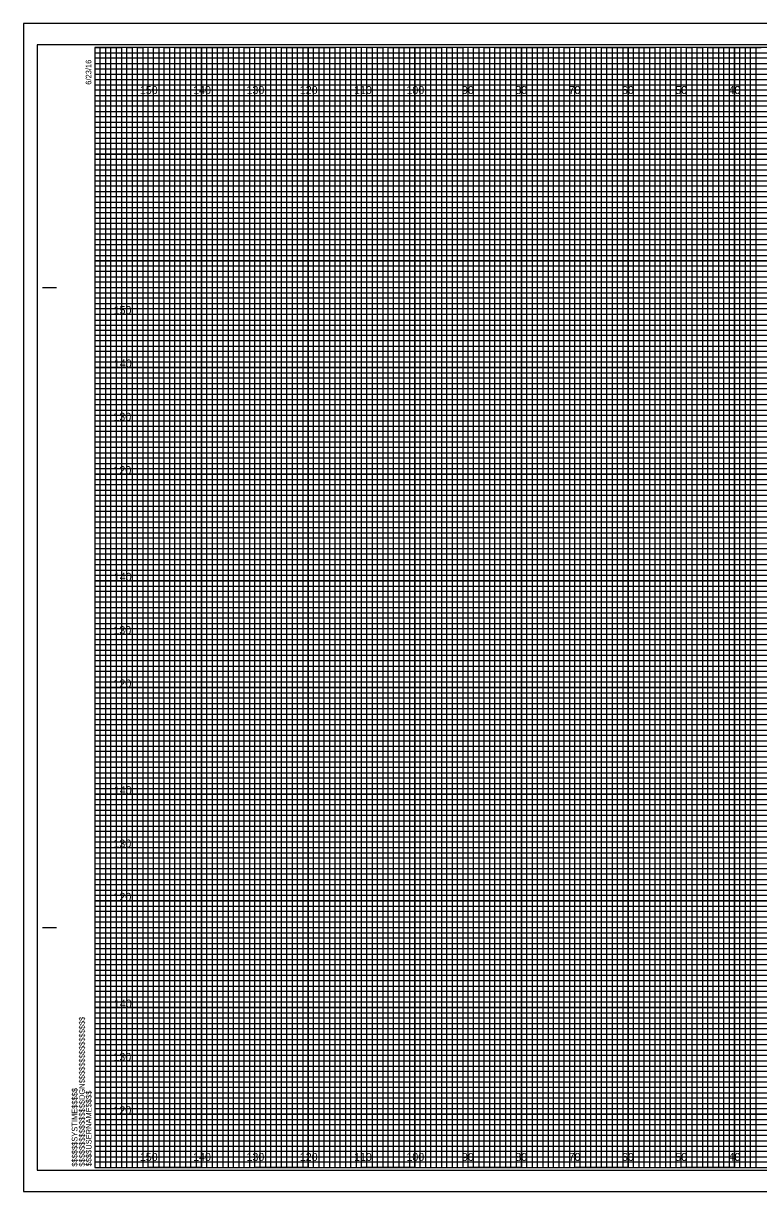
# Model space of a CAD drawing. Extents: x -13 to 323, y -5 to 1754.
# Drawn here: x -13.4 to 124.5, y -4.5 to 214.5 of the extents above; entities that cross this region are included whole.
import ezdxf

# ---------------------------------------------------------------- set-up
doc = ezdxf.new("R2010")
doc.units = 0
for name, color, linetype in [('Exist Cross Section Cell', 7, 'Continuous'), ('Exist XS Center Line Elevation Label', 7, 'Continuous'), ('Exist XS Ground Line', 7, 'Continuous'), ('Prop CMT Pvmt Course 1', 7, 'Continuous'), ('Prop CMT Pvmt Course 3', 7, 'Continuous'), ('Prop CMT Pvmt Surface', 7, 'Continuous'), ('Prop CMT Pvmt Surface Shoulder', 7, 'Continuous'), ('Prop CMT Shld Paved Course 1', 7, 'Continuous'), ('Prop CMT Shld Paved Course 2', 7, 'Continuous'), ('Prop CMT Shld Paved Course 3', 7, 'Continuous'), ('Prop CMT Subgrade Earthwork', 7, 'Continuous')]:
    doc.layers.add(name, color=color, linetype=linetype)

msp = doc.modelspace()

# ---------------------------------------------------------------- linework, layer by layer
at = {"layer": 'Exist XS Center Line Elevation Label'}
for points in [[(0, 210), (5, 210), (5, 0), (15, 0), (15, 210), (25, 210), (25, 0), (35, 0), (35, 210), (45, 210), (45, 0), (55, 0), (55, 210), (65, 210), (65, 0), (75, 0), (75, 210), (85, 210), (85, 0), (95, 0), (95, 210), (105, 210), (105, 0), (115, 0), (115, 210), (125, 210)], [(0, 205), (275, 205)], [(0, 185), (320, 185), (320, 195), (0, 195)], [(0, 165), (320, 165), (320, 175), (0, 175)], [(0, 145), (320, 145), (320, 155), (0, 155)], [(0, 125), (320, 125), (320, 135), (0, 135)], [(0, 105), (320, 105), (320, 115), (0, 115)], [(0, 85), (320, 85), (320, 95), (0, 95)], [(0, 65), (320, 65), (320, 75), (0, 75)], [(0, 45), (320, 45), (320, 55), (0, 55)], [(0, 25), (320, 25), (320, 35), (0, 35)], [(0, 5), (320, 5), (320, 15), (0, 15)]]:
    msp.add_lwpolyline(points, dxfattribs=at)
at = {"layer": 'Exist XS Ground Line'}
for p, q in [((10, 210), (0, 210)), ((10, 0), (10, 210)), ((30, 210), (20, 210)), ((20, 210), (20, 0)), ((30, 0), (30, 210)), ((50, 210), (40, 210)), ((40, 210), (40, 0)), ((50, 0), (50, 210)), ((70, 210), (60, 210)), ((60, 210), (60, 0)), ((70, 0), (70, 210)), ((90, 210), (80, 210)), ((80, 210), (80, 0)), ((90, 0), (90, 210)), ((110, 210), (100, 210)), ((100, 210), (100, 0)), ((110, 0), (110, 210)), ((130, 210), (120, 210)), ((120, 210), (120, 0)), ((20, 0), (10, 0)), ((40, 0), (30, 0)), ((60, 0), (50, 0)), ((80, 0), (70, 0)), ((100, 0), (90, 0)), ((120, 0), (110, 0))]:
    msp.add_line(p, q, dxfattribs=at)
for points in [[(0, 200), (320, 200), (320, 190), (0, 190)], [(0, 180), (320, 180), (320, 170), (0, 170)], [(0, 160), (320, 160), (320, 150), (0, 150)], [(0, 140), (320, 140), (320, 130), (0, 130)], [(0, 120), (320, 120), (320, 110), (0, 110)], [(0, 100), (320, 100), (320, 90), (0, 90)], [(0, 80), (320, 80), (320, 70), (0, 70)], [(0, 60), (320, 60), (320, 50), (0, 50)], [(0, 40), (320, 40), (320, 30), (0, 30)], [(0, 20), (320, 20), (320, 10), (0, 10)]]:
    msp.add_lwpolyline(points, dxfattribs=at)
at = {"layer": 'Prop CMT Pvmt Course 3'}
msp.add_lwpolyline([(-13.4, -4.5), (323.3, -4.5), (323.3, 214.5), (-13.4, 214.5)], close=True, dxfattribs=at)
at = {"layer": 'Prop CMT Pvmt Surface'}
for p, q in [((10, 0), (10, 210)), ((20, 0), (20, 210)), ((30, 0), (30, 210)), ((40, 0), (40, 210)), ((50, 0), (50, 210)), ((60, 0), (60, 210)), ((70, 0), (70, 210)), ((80, 0), (80, 210)), ((90, 0), (90, 210)), ((100, 0), (100, 210)), ((110, 0), (110, 210)), ((120, 0), (120, 210)), ((0, 200), (320, 200)), ((0, 190), (320, 190)), ((0, 180), (320, 180)), ((0, 170), (320, 170)), ((0, 160), (320, 160)), ((0, 150), (320, 150)), ((0, 140), (320, 140)), ((0, 130), (320, 130)), ((0, 120), (320, 120)), ((0, 110), (320, 110)), ((0, 100), (320, 100)), ((0, 90), (320, 90)), ((0, 80), (320, 80)), ((0, 70), (320, 70)), ((0, 60), (320, 60)), ((0, 50), (320, 50)), ((0, 40), (320, 40)), ((0, 30), (320, 30)), ((0, 20), (320, 20)), ((0, 10), (320, 10))]:
    msp.add_line(p, q, dxfattribs=at)
at = {"layer": 'Prop CMT Pvmt Surface Shoulder'}
for p, q in [((323.3, 214.5), (-13.4, 214.5)), ((-13.4, 214.5), (-13.4, -4.5)), ((-13.4, -4.5), (323.3, -4.5))]:
    msp.add_line(p, q, dxfattribs=at)
at = {"layer": 'Prop CMT Shld Paved Course 1'}
for p, q in [((0, 209), (260, 209)), ((260, 207.98), (0, 207.98)), ((0, 207.98), (0, 207)), ((0, 207), (260, 207)), ((260, 205.89), (0, 205.89)), ((0, 205.89), (0, 204)), ((0, 204), (320, 204))]:
    msp.add_line(p, q, dxfattribs=at)
for points in [[(0, 203), (270, 203), (320, 203), (320, 202), (0, 202)], [(0, 201), (320, 201), (320, 199), (0, 199)], [(0, 198), (320, 198), (320, 197), (0, 196.98)], [(0, 196), (320, 196), (320, 194), (0, 194)], [(0, 193), (320, 193), (320, 192), (0, 192)], [(0, 191), (320, 191), (320, 189), (0, 189)], [(0, 188), (320, 188), (320, 187), (0, 187)], [(0, 186), (320, 186), (320, 184), (0, 184)], [(0, 183), (320, 183), (320, 182), (0, 182)], [(0, 181), (320, 181), (320, 179), (0, 179)], [(0, 178), (320, 178), (320, 177), (0, 177)], [(0, 176), (320, 176), (320, 173.95), (320, 173), (320, 172), (0, 172)], [(0, 174), (320, 174), (320, 173), (0, 173)], [(0, 171), (320, 171), (320, 169), (0, 169.03)], [(0, 169.03), (320, 169), (320, 168), (0, 168)], [(0, 167), (320, 167), (320, 166), (0, 166)], [(0, 164), (320, 164), (320, 163), (0, 163)], [(0, 162), (320, 162), (320, 161), (0, 161)], [(-0.07, 158.89), (320, 158.89), (320, 157.88), (-0.07, 157.88)], [(0, 157), (320, 157), (320, 156), (0, 156)], [(0, 154), (320, 154), (320, 153), (0, 153)], [(0, 152), (320, 152), (320, 151), (0, 151)], [(0, 149), (320, 149), (320, 148), (0, 148)], [(0, 147), (320, 147), (320, 146), (0, 146)], [(0, 144), (320, 144), (320, 143), (0, 143)], [(0, 142), (320, 142), (320, 141), (0, 141)], [(0, 139), (320, 139), (319.99, 137.98), (0, 138)], [(0, 137), (320, 137), (320, 136), (0, 136)], [(0, 134), (320, 134), (320, 133), (0, 133)], [(0, 132), (320, 132), (320, 131), (0, 131)], [(0, 129), (320, 129), (320, 128), (0, 128)], [(0, 127), (320, 127), (320, 126), (0, 126)], [(0, 124), (320, 124), (320, 123), (0, 123)], [(0, 122), (320, 122), (320, 121), (0, 121)], [(0, 119), (320, 119), (320, 118), (0, 118)], [(0, 116.99), (320.07, 116.91), (320, 116), (0, 116)], [(0, 114), (320, 114), (320, 113), (0, 113)], [(0, 112), (320, 112), (320, 111), (0, 111)], [(0, 109), (320, 109), (320, 108), (0, 108)], [(0, 107), (320, 107), (320, 106), (0, 106)], [(0, 104), (320, 104), (320, 103), (0, 103)], [(0, 102), (320, 102), (320, 101), (0, 101)], [(0, 99), (320, 99), (320, 98), (0, 98)], [(0, 97), (320, 97), (320, 96), (0, 96)], [(0, 94), (320, 94), (320, 93), (0, 93)], [(0, 92), (320, 92), (320, 91), (0, 91)], [(0, 89), (320, 89), (320, 88), (0, 88)], [(0, 87), (320, 87), (320, 86), (0, 86)], [(0, 84), (320, 84), (320, 83), (0, 83)], [(0, 82), (320, 82), (320, 81), (0, 81)], [(0, 79), (320, 79), (319.99, 77.98), (0, 78)], [(0, 77), (320, 77), (320, 76), (0, 76)], [(0, 74), (320, 74), (320, 73), (0, 73)], [(0, 72), (320, 72), (320, 71), (0, 71)], [(0, 69), (320, 69), (320, 68), (0, 68)], [(0, 67), (320, 67), (320, 66), (0, 66)], [(0, 64), (320, 64), (320, 63), (0, 63)], [(0, 62), (320, 62), (320, 61), (0, 61)], [(0, 59), (320, 59), (320, 58), (0, 58)], [(0, 56.99), (320.07, 56.91), (320, 56), (0, 56)], [(0, 54), (320, 54), (320, 53), (0, 53)], [(0, 52), (320, 52), (320, 51), (0, 51)], [(0, 49), (320, 49), (320, 48), (0, 48)], [(0, 47), (320, 47), (320, 46), (0, 46)], [(0, 44), (320, 44), (320, 43), (0, 43)], [(0, 42), (320, 42), (320, 41), (0, 41)], [(0, 39), (320, 39), (320, 38), (0, 38)], [(0, 37), (320, 37), (320, 36), (0, 36)], [(0, 34), (320, 34), (320, 33), (0, 33)], [(0, 32), (320, 32), (320, 31), (0, 31)], [(0, 29), (320, 29), (320, 28), (0, 28)], [(0, 27), (320, 27), (320, 26), (0, 26)], [(0, 24), (320, 24), (320, 23), (0, 23)], [(0, 22), (320, 22), (320, 21), (0, 21)], [(0, 19), (320, 19), (320, 18), (0, 18)], [(0, 17), (320, 17), (320, 16), (0, 16)], [(0, 14), (320, 14), (320, 13), (0, 13)], [(0, 12), (320, 12), (320, 11), (0, 11)], [(0, 9), (320, 9), (320, 8), (0, 8)], [(0, 7), (320, 7), (320, 6), (0, 6)], [(0, 4), (320, 4), (320, 3), (0, 3)], [(0, 2), (320, 2), (320, 1), (0, 1)]]:
    msp.add_lwpolyline(points, dxfattribs=at)
at = {"layer": 'Prop CMT Shld Paved Course 2'}
for p, q in [((-9.8, 165), (-7.3, 165)), ((-9.7, 165), (-7.2, 165)), ((-9.8, 45), (-7.3, 45)), ((-9.7, 45), (-7.2, 45)), ((0, 0), (0, 0)), ((0, 0), (0, 0)), ((0, 0), (0, 0)), ((0, 0), (0, 0)), ((0, 0), (0, 0)), ((0, 0), (0, 0)), ((0, 0), (0, 0))]:
    msp.add_line(p, q, dxfattribs=at)
msp.add_lwpolyline([(320, 210), (0, 210), (0, 0), (320, 0)], close=True, dxfattribs=at)
at = {"layer": 'Prop CMT Shld Paved Course 3'}
for points in [[(0, 0), (1, 0), (1, 210), (2, 210), (2, 0)], [(2, 0), (3, 0), (3, 210), (4, 210), (4, 0)], [(5, 0), (6, 0), (6, 210), (7, 210), (7, 0)], [(7, 0), (8, 0), (8, 210), (9, 210), (9, 0)], [(10, 0), (11, 0), (11, 210), (12, 210), (12, 0)], [(12, 0), (13, 0), (13, 210), (14, 210), (14, 0)], [(15, 0), (16, 0), (16, 210), (17, 210), (17, 0)], [(17, 0), (18, 0), (18, 210), (19, 210), (19, 0)], [(20, 0), (21, 0), (21, 210), (22, 210), (22, 0)], [(22, 0), (23, 0), (23, 210), (24, 210), (24, 0)], [(25, 0), (26, 0), (26, 210), (27, 210), (27, 0)], [(27, 0), (28, 0), (28, 210), (29, 210), (29, 0)], [(30, 0), (31, 0), (31, 210), (32, 210), (32, 0)], [(32, 0), (33, 0), (33, 210), (34, 210), (34, 0)], [(35, 0), (36, 0), (36, 210), (37, 210), (37, 0)], [(37, 0), (38, 0), (38, 210), (39, 210), (39, 0)], [(40, 0), (41, 0), (41, 210), (42, 210), (42, 0)], [(42, 0), (43, 0), (43, 210), (44, 210), (44, 0)], [(45, 0), (46, 0), (46, 210), (47, 210), (47, 0)], [(47, 0), (48, 0), (48, 210), (49, 210), (49, 0)], [(50, 0), (51, 0), (51, 210), (52, 210), (52, 0)], [(52, 0), (53, 0), (53, 210), (54, 210), (54, 0)], [(55, 0), (56, 0), (56, 210), (57, 210), (57, 0)], [(57, 0), (58, 0), (58, 210), (59, 210), (59, 0)], [(60, 0), (61, 0), (61, 210), (62, 210), (62, 0)], [(62, 0), (63, 0), (63, 210), (64, 210), (64, 0)], [(65, 0), (66, 0), (66, 210), (67, 210), (67, 0)], [(67, 0), (68, 0), (68, 210), (69, 210), (69, 0)], [(70, 0), (71, 0), (71, 210), (72, 210), (72, 0)], [(72, 0), (73, 0), (73, 210), (74, 210), (74, 0)], [(75, 0), (76, 0), (76, 210), (77, 210), (77, 0)], [(77, 0), (78, 0), (78, 210), (79, 210), (79, 0)], [(80, 0), (81, 0), (81, 210), (82, 210), (82, 0)], [(82, 0), (83, 0), (83, 210), (84, 210), (84, 0)], [(85, 0), (86, 0), (86, 210), (87, 210), (87, 0)], [(87, 0), (88, 0), (88, 210), (89, 210), (89, 0)], [(90, 0), (91, 0), (91, 210), (92, 210), (92, 0)], [(92, 0), (93, 0), (93, 210), (94, 210), (94, 0)], [(95, 0), (96, 0), (96, 210), (97, 210), (97, 0)], [(97, 0), (98, 0), (98, 210), (99, 210), (99, 0)], [(100, 0), (101, 0), (101, 210), (102, 210), (102, 0)], [(102, 0), (103, 0), (103, 210), (104, 210), (104, 0)], [(105, 0), (106, 0), (106, 210), (107, 210), (107, 0)], [(107, 0), (108, 0), (108, 210), (109, 210), (109, 0)], [(110, 0), (111, 0), (111, 210), (112, 210), (112, 0)], [(112, 0), (113, 0), (113, 210), (114, 210), (114, 0)], [(115, 0), (116, 0), (116, 210), (117, 210), (117, 0)], [(117, 0), (118, 0), (118, 210), (119, 210), (119, 0)], [(120, 0), (121, 0), (121, 210), (122, 210), (122, 0)], [(122, 0), (123, 0), (123, 210), (124, 210), (124, 0)]]:
    msp.add_lwpolyline(points, dxfattribs=at)
at = {"layer": 'Prop CMT Subgrade Earthwork'}
msp.add_lwpolyline([(-10.8, -0.5), (322.4, -0.5), (322.4, 210.5), (-10.8, 210.5)], close=True, dxfattribs=at)

# ---------------------------------------------------------------- texts
at = {"layer": 'Exist Cross Section Cell'}
for s, p in [('150', (8.44, 201.25)), ('140', (18.44, 201.25)), ('130', (28.44, 201.25)), ('120', (38.44, 201.25)), ('110', (48.62, 201.25)), ('100', (58.44, 201.25)), ('90', (68.86, 201.25)), ('80', (78.86, 201.25)), ('70', (88.86, 201.25)), ('60', (98.86, 201.25)), ('50', (108.86, 201.25)), ('40', (118.86, 201.25)), ('150', (8.44, 1.25)), ('140', (18.44, 1.25)), ('130', (28.44, 1.25)), ('120', (38.44, 1.25)), ('110', (48.62, 1.25)), ('100', (58.44, 1.25)), ('90', (68.86, 1.25)), ('80', (78.86, 1.25)), ('70', (88.86, 1.25)), ('60', (98.86, 1.25)), ('50', (108.86, 1.25)), ('40', (118.86, 1.25))]:
    msp.add_text(s, height=1.5, dxfattribs=at).set_placement(p)
at = {"layer": 'Prop CMT Pvmt Course 1'}
for s, p in [('150', (3.52, 160)), ('140', (3.57, 150)), ('130', (3.49, 140)), ('120', (3.5, 130)), ('140', (3.57, 110)), ('130', (3.49, 100)), ('120', (3.5, 90)), ('140', (3.57, 70)), ('130', (3.49, 60)), ('120', (3.5, 50)), ('140', (3.57, 30)), ('130', (3.49, 20)), ('120', (3.5, 10))]:
    msp.add_text(s, height=1.5, dxfattribs=at).set_placement(p)
at = {"layer": 'Prop CMT Shld Paved Course 2'}
for s, p in [('6/23/16', (-0.65, 203)), ('$$$$$$$$$$$$$$$$DGN$$$$$$$$$$$$$$$$', (-1.88, 0.18)), ('$$$$$$SYSTIME$$$$$', (-3.26, 0.18)), ('$$$$USERNAME$$$$', (-0.62, 0.23))]:
    msp.add_text(s, height=1.05, rotation=90, dxfattribs=at).set_placement(p)

doc.saveas('drawing.dxf')
